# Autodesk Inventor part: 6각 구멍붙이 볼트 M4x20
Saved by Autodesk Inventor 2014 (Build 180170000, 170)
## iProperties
Created: 2026-05
Part Number: 6각 구멍붙이 볼트 M4x20
Material: 일반
Document SubType Name: Modeling
Designer: dg
Density: 1 g/cm^3
Appearance: 기본값
Author: dg
Author: jhkim
Description: 6각머리 태핑 나사
Creation Date: 2026-04-27
Sending System: Autodesk Inventor 2027
Preprocessor: ST-DEVELOPER v20.1
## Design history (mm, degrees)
node "6각 구멍붙이 볼트 M4x201"
body "Solid1"
node "기준1"
